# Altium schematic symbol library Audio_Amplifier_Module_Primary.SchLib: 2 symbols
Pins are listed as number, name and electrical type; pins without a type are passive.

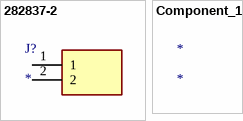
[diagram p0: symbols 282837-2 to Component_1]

## 282837-2
designator J?
Connector; Manufacturer_Name: TE Connectivity; Manufacturer_Part_Number: 282837-2; Description: Body Features: Product Orientation Vertical ¦ Primary Product Color Green ¦ Configuration Features: Wire Entry Location Side ¦ Stacking Configuration Side Stackable ¦ Number of Rows 1 ¦ Stacked Levels Without ¦ Number of Positions 2 ¦ Wire Entry Angle 90 ¦ Contact Features: Contact Current Rating (Max) 13.5 AMP ¦ Contact Mating Area Plating Material Tin ¦ Contact Base Material Brass ¦ Dimensions: Wire Size 30  16 AWG ¦ Wire Size .05  1.3 MMSQ ¦ Electrical Characteristics: Operating Voltage 300 VAC ¦
footprint 2828372
pins: 1, 2

## Component_1
designator *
